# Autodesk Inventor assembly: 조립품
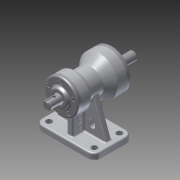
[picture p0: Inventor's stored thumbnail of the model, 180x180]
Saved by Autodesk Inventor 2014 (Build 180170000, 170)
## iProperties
Created: 2015-08
Part Number: 조립품
Document SubType Name: Assembly
Designer: SCD-A09
Author: SCD-A09
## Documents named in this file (10)
- C:\Users\SCD-A09\Desktop\450805V1013\조립품.iam
- C:\Users\SCD-A09\Desktop\450805V1013\본체.ipt
- C:\Users\SCD-A09\Desktop\450805V1013\M4x0.5.ipt
- C:\Users\SCD-A09\Desktop\450805V1013\뒤커버.ipt
- C:\Users\SCD-A09\Desktop\450805V1013\베어링 6203.ipt
- C:\Users\SCD-A09\Desktop\450805V1013\베어링 6205.ipt
- C:\Users\SCD-A09\Desktop\450805V1013\앞커버.ipt
- C:\Users\SCD-A09\Desktop\450805V1013\오일실 .ipt
- 오일실 .ipt
- C:\Users\SCD-A09\Desktop\450805V1013\축.ipt
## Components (10 placed, 1 different names)
1. M4x0.5:1
2. M4x0.5:3
3. M4x0.5:4
4. M4x0.5:5
5. M4x0.5:6
6. M4x0.5:2
7. M4x0.5:7
8. M4x0.5:8
9. M4x0.5:9
10. M4x0.5:10
